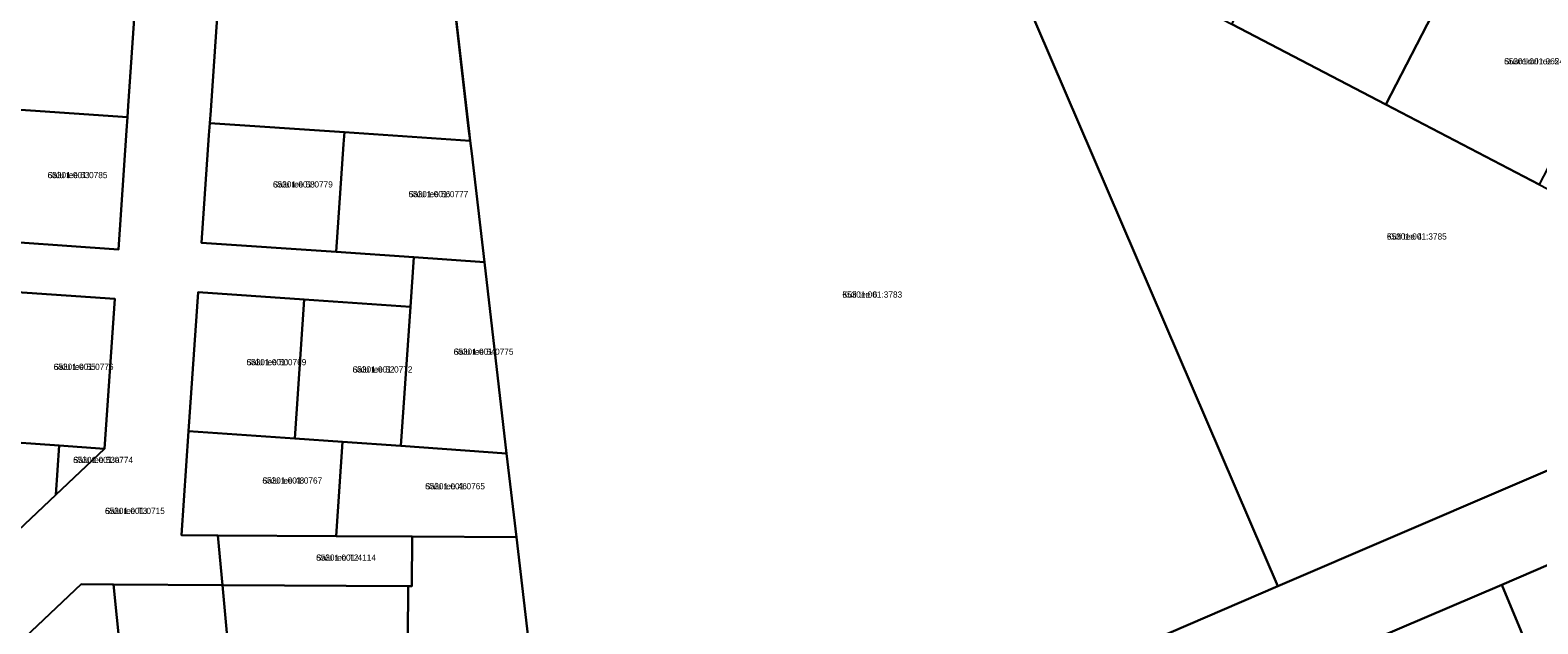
# Model space of a CAD drawing. Extents: x 543236 to 563717, y 6566033 to 6588992.
# Drawn here: x 545424.5 to 545789.8, y 6584611.9 to 6584755.7 of the extents above; entities that cross this region are included whole.
import ezdxf

# ---------------------------------------------------------------- set-up
doc = ezdxf.new("R2010")
doc.units = 0
for name, color, linetype in [('L_AADRESS', 7, 'Continuous'), ('PIIR', 7, 'Continuous'), ('TUNNUS', 7, 'Continuous')]:
    doc.layers.add(name, color=color, linetype=linetype)

msp = doc.modelspace()

# ---------------------------------------------------------------- linework, layer by layer
at = {"layer": 'PIIR'}
for points in [[(545522.71, 6584801.88), (545515.72, 6584861.42), (545540.95, 6584848.28), (545568.44, 6584833.94), (545595.9, 6584819.6), (545623.37, 6584805.21), (545650.89, 6584790.87), (545654.59, 6584788.95), (545726.79, 6584620.99), (545552.43, 6584545.79), (545548.01, 6584583.61), (545542.31, 6584632.89), (545539.87, 6584653.16), (545534.53, 6584699.52), (545531.48, 6584725.86), (545531.11, 6584728.87), (545530.7, 6584731.91)], [(545386.81, 6584811.27), (545453, 6584806.71), (545448.22, 6584737.35), (545448.03, 6584734.59), (545411.55, 6584737.1), (545375.78, 6584739.56), (545386, 6584805.97)], [(545472.95, 6584805.34), (545522.71, 6584801.88), (545530.76, 6584731.87), (545531.11, 6584728.87), (545500.59, 6584730.97), (545467.99, 6584733.21), (545468.2, 6584736.24)], [(545735.71, 6584795.89), (545772.99, 6584776.54), (545752.91, 6584737.72), (545715.64, 6584757.18)], [(545726.79, 6584620.99), (545654.59, 6584788.95), (545678.32, 6584776.54), (545715.64, 6584757.18), (545752.91, 6584737.72), (545790.07, 6584718.33), (545827.29, 6584698.94), (545872.72, 6584675.22), (545839.95, 6584669.53)], [(545772.99, 6584776.54), (545810.27, 6584757.2), (545790.07, 6584718.33), (545752.91, 6584737.72)], [(545411.55, 6584737.1), (545448.03, 6584734.59), (545447.81, 6584731.36), (545445.83, 6584702.6), (545409.35, 6584705.11), (545411.31, 6584733.62)], [(545467.99, 6584733.21), (545500.59, 6584730.97), (545500.39, 6584728.06), (545498.59, 6584701.97), (545465.99, 6584704.22), (545467.78, 6584730.26)], [(545500.59, 6584730.97), (545531.11, 6584728.87), (545531.48, 6584725.86), (545534.53, 6584699.52), (545517.43, 6584700.68), (545498.59, 6584701.97), (545500.39, 6584728.06)], [(545517.43, 6584700.68), (545534.53, 6584699.52), (545539.87, 6584653.16), (545514.28, 6584655.02), (545516.6, 6584688.7)], [(545417.81, 6584692.5), (545445.01, 6584690.63), (545442.51, 6584654.3), (545431.47, 6584655.06), (545415.31, 6584656.18)], [(545465.17, 6584692.24), (545490.88, 6584690.47), (545488.57, 6584656.79), (545462.85, 6584658.56)], [(545490.88, 6584690.47), (545516.6, 6584688.7), (545514.28, 6584655.02), (545500.17, 6584656), (545488.57, 6584656.79)], [(545554.87, 6584524.21), (545552.43, 6584545.79), (545726.79, 6584620.99), (545839.95, 6584669.53), (545872.72, 6584675.22), (545888.44, 6584667.02), (545877.22, 6584662.72), (545831.24, 6584642.97), (545781.01, 6584621.34), (545744.13, 6584605.54), (545732.55, 6584600.53), (545727.05, 6584598.13), (545698.86, 6584586.05), (545669.91, 6584573.6), (545623.89, 6584553.85), (545600.84, 6584543.9)], [(545381.51, 6584634.53), (545403.99, 6584656.95), (545415.31, 6584656.18), (545431.47, 6584655.06), (545430.65, 6584643.12), (545404.83, 6584618.77)], [(545462.85, 6584658.56), (545488.57, 6584656.79), (545500.17, 6584656), (545498.6, 6584633.13), (545469.97, 6584633.28), (545461.11, 6584633.33)], [(545431.47, 6584655.06), (545442.51, 6584654.3), (545430.65, 6584643.12)], [(545500.17, 6584656), (545514.28, 6584655.02), (545539.87, 6584653.16), (545542.31, 6584632.89), (545516.98, 6584633.03), (545498.6, 6584633.13)], [(545831.24, 6584642.97), (545836.74, 6584614.39), (545838.5, 6584605.23), (545795.24, 6584587.14), (545781.01, 6584621.34)], [(545469.97, 6584633.28), (545498.6, 6584633.13), (545516.98, 6584633.03), (545516.91, 6584621.03), (545516.02, 6584621.03), (545471.07, 6584621.27)], [(545516.98, 6584633.03), (545542.31, 6584632.89), (545548.01, 6584583.61), (545516.7, 6584583.77), (545515.81, 6584583.77), (545516.02, 6584621.03), (545516.91, 6584621.03)], [(545420.17, 6584605.74), (545436.83, 6584621.46), (545444.63, 6584621.42), (545448.67, 6584581.39), (545405.37, 6584577.02), (545410.89, 6584592.01)], [(545444.63, 6584621.42), (545471.07, 6584621.27), (545474.47, 6584583.99), (545448.67, 6584581.39)], [(545471.07, 6584621.27), (545516.02, 6584621.03), (545515.81, 6584583.77), (545510.77, 6584583.8), (545474.47, 6584583.99)], [(545781.01, 6584621.34), (545795.24, 6584587.14), (545758.67, 6584571.84), (545744.13, 6584605.54)]]:
    msp.add_lwpolyline(points, close=True, dxfattribs=at)
for points in [[(545409.35, 6584705.11), (545445.83, 6584702.6), (545447.81, 6584731.36), (545448.03, 6584734.59), (545448.22, 6584737.35), (545453, 6584806.71)], [(545472.95, 6584805.34), (545468.2, 6584736.24), (545467.99, 6584733.21), (545467.78, 6584730.26), (545465.99, 6584704.22), (545498.59, 6584701.97), (545517.43, 6584700.68), (545516.6, 6584688.7), (545490.88, 6584690.47), (545465.17, 6584692.24), (545462.85, 6584658.56), (545461.11, 6584633.33), (545469.97, 6584633.28), (545471.07, 6584621.27), (545444.63, 6584621.42), (545436.83, 6584621.46), (545420.17, 6584605.74)], [(545404.83, 6584618.77), (545430.65, 6584643.12), (545442.51, 6584654.3), (545445.01, 6584690.63), (545417.81, 6584692.5)]]:
    msp.add_lwpolyline(points, dxfattribs=at)

# ---------------------------------------------------------------- texts
at = {"layer": 'L_AADRESS'}
for s, p in [('Suurekivi tee 5', (545781.59, 6584747.42)), ('Salu tee 63', (545428.69, 6584719.85)), ('Salu tee 58', (545483.29, 6584717.59)), ('Salu tee 56', (545516.11, 6584715.24)), ('Küti tee 4', (545753.2, 6584704.97)), ('Küti tee 6', (545621.25, 6584690.9)), ('Salu tee 54', (545527.07, 6584677.06)), ('Salu tee 55', (545430.16, 6584673.4)), ('Salu tee 50', (545476.87, 6584674.52)), ('Salu tee 52', (545502.59, 6584672.75)), ('Salu tee 53a', (545434.88, 6584650.83)), ('Salu tee 48', (545480.72, 6584645.84)), ('Salu tee 46', (545520.15, 6584644.45)), ('Salu tee T3', (545442.59, 6584638.48)), ('Salu tee T2', (545493.74, 6584627.16))]:
    msp.add_text(s, height=1.5, dxfattribs=at).set_placement(p)
at = {"layer": 'TUNNUS'}
for s, p in [('65301:001:0624', (545781.59, 6584747.42)), ('65301:001:0785', (545428.69, 6584719.85)), ('65301:001:0779', (545483.29, 6584717.59)), ('65301:001:0777', (545516.11, 6584715.24)), ('65301:001:3785', (545753.2, 6584704.97)), ('65301:001:3783', (545621.25, 6584690.9)), ('65301:001:0775', (545527.07, 6584677.06)), ('65301:001:0776', (545430.16, 6584673.4)), ('65301:001:0769', (545476.87, 6584674.52)), ('65301:001:0772', (545502.59, 6584672.75)), ('65301:001:0774', (545434.88, 6584650.83)), ('65301:001:0767', (545480.72, 6584645.84)), ('65301:001:0765', (545520.15, 6584644.45)), ('65301:001:0715', (545442.59, 6584638.48)), ('65301:001:4114', (545493.74, 6584627.16))]:
    msp.add_text(s, height=1.5, dxfattribs=at).set_placement(p)

doc.saveas('drawing.dxf')
